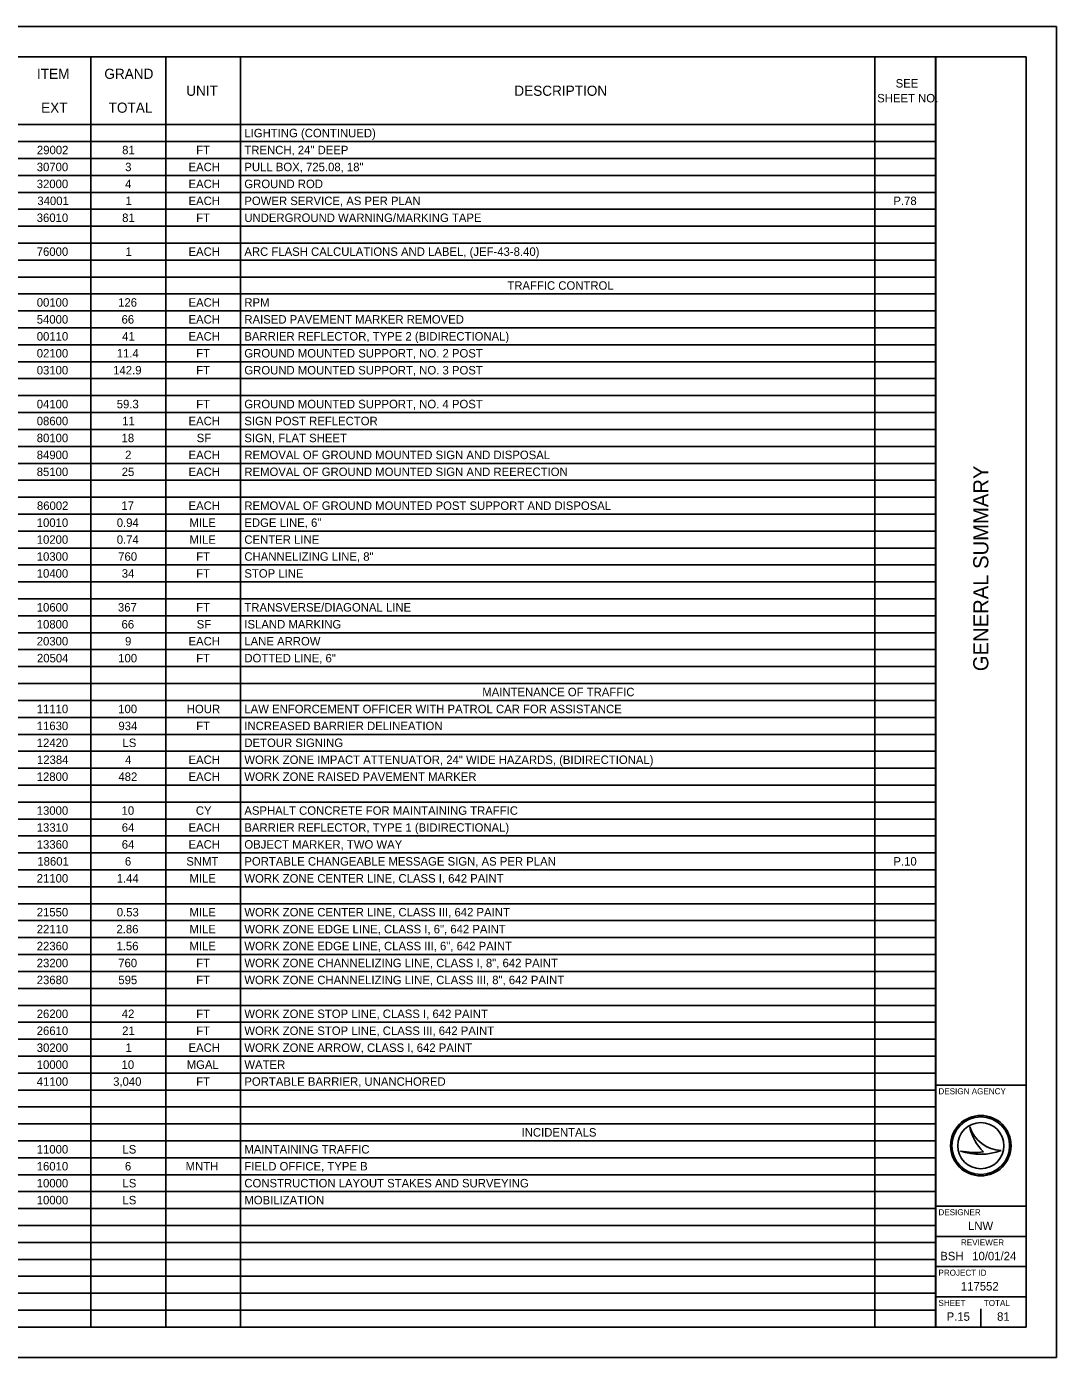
# Model space of a CAD drawing. Extents: x 0 to 34, y 0 to 22.
# Drawn here: x 16.97 to 34, y 0 to 22 of the extents above; entities that cross this region are included whole.
import ezdxf

# ---------------------------------------------------------------- set-up
doc = ezdxf.new("R2010")
doc.units = 0
for name, color, linetype in [('Default', 7, 'Continuous'), ('SH_Border', 7, 'Continuous'), ('SH_Cut_Line', 7, 'Continuous'), ('SH_Data', 7, 'Continuous')]:
    doc.layers.add(name, color=color, linetype=linetype)

msp = doc.modelspace()

# ---------------------------------------------------------------- linework, layer by layer
at = {"layer": 'Default'}
for p, q in [((1.5, 21.5), (32.004, 21.5)), ((18.036, 21.5), (18.036, 0.5)), ((19.272, 21.5), (19.272, 0.5)), ((20.507, 21.5), (20.507, 0.5)), ((30.999, 21.5), (30.999, 0.5)), ((32.004, 21.5), (32.004, 0.5)), ((1.5, 20.38), (32.004, 20.38)), ((1.5, 20.1), (32.004, 20.1)), ((1.5, 19.82), (32.004, 19.82)), ((1.5, 19.54), (32.004, 19.54)), ((1.5, 19.26), (32.004, 19.26)), ((1.5, 18.98), (32.004, 18.98)), ((1.5, 18.7), (32.004, 18.7)), ((1.5, 18.42), (32.004, 18.42)), ((1.5, 18.14), (32.004, 18.14)), ((1.5, 17.86), (32.004, 17.86)), ((1.5, 17.58), (32.004, 17.58)), ((1.5, 17.3), (32.004, 17.3)), ((1.5, 17.02), (32.004, 17.02)), ((1.5, 16.74), (32.004, 16.74)), ((1.5, 16.46), (32.004, 16.46)), ((1.5, 16.18), (32.004, 16.18)), ((1.5, 15.9), (32.004, 15.9)), ((1.5, 15.62), (32.004, 15.62)), ((1.5, 15.34), (32.004, 15.34)), ((1.5, 15.06), (32.004, 15.06)), ((1.5, 14.78), (32.004, 14.78)), ((1.5, 14.5), (32.004, 14.5)), ((1.5, 14.22), (32.004, 14.22)), ((1.5, 13.94), (32.004, 13.94)), ((1.5, 13.66), (32.004, 13.66)), ((1.5, 13.38), (32.004, 13.38)), ((1.5, 13.1), (32.004, 13.1)), ((1.5, 12.82), (32.004, 12.82)), ((1.5, 12.54), (32.004, 12.54)), ((1.5, 12.26), (32.004, 12.26)), ((1.5, 11.98), (32.004, 11.98)), ((1.5, 11.7), (32.004, 11.7)), ((1.5, 11.42), (32.004, 11.42)), ((1.5, 11.14), (32.004, 11.14)), ((1.5, 10.86), (32.004, 10.86)), ((1.5, 10.58), (32.004, 10.58)), ((1.5, 10.3), (32.004, 10.3)), ((1.5, 10.02), (32.004, 10.02)), ((1.5, 9.74), (32.004, 9.74)), ((1.5, 9.46), (32.004, 9.46)), ((1.5, 9.18), (32.004, 9.18)), ((1.5, 8.9), (32.004, 8.9)), ((1.5, 8.62), (32.004, 8.62)), ((1.5, 8.34), (32.004, 8.34)), ((1.5, 8.06), (32.004, 8.06)), ((1.5, 7.78), (32.004, 7.78)), ((1.5, 7.5), (32.004, 7.5)), ((1.5, 7.22), (32.004, 7.22)), ((1.5, 6.94), (32.004, 6.94)), ((1.5, 6.66), (32.004, 6.66)), ((1.5, 6.38), (32.004, 6.38)), ((1.5, 6.1), (32.004, 6.1)), ((1.5, 5.82), (32.004, 5.82)), ((1.5, 5.54), (32.004, 5.54)), ((1.5, 5.26), (32.004, 5.26)), ((1.5, 4.98), (32.004, 4.98)), ((1.5, 4.7), (32.004, 4.7)), ((1.5, 4.42), (32.004, 4.42)), ((1.5, 4.14), (32.004, 4.14)), ((1.5, 3.86), (32.004, 3.86)), ((1.5, 3.58), (32.004, 3.58)), ((1.5, 3.3), (32.004, 3.3)), ((1.5, 3.02), (32.004, 3.02)), ((1.5, 2.74), (32.004, 2.74)), ((1.5, 2.46), (32.004, 2.46)), ((1.5, 2.18), (32.004, 2.18)), ((1.5, 1.9), (32.004, 1.9)), ((1.5, 1.62), (32.004, 1.62)), ((1.5, 1.34), (32.004, 1.34)), ((1.5, 1.06), (32.004, 1.06)), ((1.5, 0.78), (32.004, 0.78)), ((1.5, 0.5), (32.004, 0.5))]:
    msp.add_line(p, q, dxfattribs=at)
at = {"layer": 'SH_Border'}
for p, q in [((32, 0.5), (32, 21.5)), ((32, 4.5), (33.5, 4.5)), ((32, 2.5), (33.5, 2.5)), ((32, 2), (33.5, 2)), ((32, 1.5), (33.5, 1.5)), ((32, 1), (33.5, 1))]:
    msp.add_line(p, q, dxfattribs=at)
msp.add_lwpolyline([(1.5, 21.5), (33.5, 21.5), (33.5, 0.5), (1.5, 0.5)], close=True, dxfattribs=at)
at = {"layer": 'SH_Cut_Line'}
msp.add_lwpolyline([(0, 0), (34, 0), (34, 22), (0, 22)], close=True, dxfattribs=at)
at = {"layer": 'SH_Data'}
for p, q in [((32.567, 3.81), (32.567, 3.81)), ((32.417, 3.41), (32.417, 3.41)), ((32.75, 3.5), (32.75, 3.5)), ((33.087, 3.419), (33.087, 3.419)), ((32.375, 0.675), (32.375, 0.675)), ((32.75, 0.5), (32.75, 0.8))]:
    msp.add_line(p, q, dxfattribs=at)
for radius in [0.5, 0.477, 0.477, 0.382]:
    msp.add_circle((32.75, 3.5), radius, dxfattribs=at)
for centre, radius, start, end in [((33.116, 3.998), 0.58, 198.9257, 198.9319), ((33.347, 3.97), 0.796, 191.6379, 191.6421), ((33.116, 3.998), 0.58, 198.9319, 267.1657), ((33.347, 3.97), 0.796, 191.6421, 226.0947), ((32.739, 4.37), 1.013, 251.4576, 290.0832), ((32.648, 4.654), 1.266, 259.4964, 259.4995), ((32.739, 4.37), 1.013, 251.4527, 251.4576), ((32.648, 4.654), 1.266, 259.4995, 276.6672)]:
    msp.add_arc(centre, radius, start, end, dxfattribs=at)

# ---------------------------------------------------------------- texts
at = {"layer": 'Default'}
for s, height, p in [('ITEM', 0.168, (17.144, 21.136)), ('GRAND', 0.168, (18.258, 21.136)), ('SEE ', 0.14, (31.342, 20.992)), ('UNIT', 0.168, (19.612, 20.856)), ('DESCRIPTION', 0.168, (25.037, 20.856)), ('EXT', 0.168, (17.212, 20.576)), ('TOTAL', 0.168, (18.329, 20.576)), ('SHEET NO.', 0.14, (31.037, 20.747)), ('LIGHTING (CONTINUED)', 0.14, (20.573, 20.17)), ('29002', 0.14, (17.143, 19.89)), ('81', 0.14, (18.552, 19.89)), ('FT', 0.14, (19.777, 19.89)), ('TRENCH, 24" DEEP', 0.14, (20.573, 19.89)), ('30700', 0.14, (17.14, 19.61)), ('3', 0.14, (18.602, 19.61)), ('EACH', 0.14, (19.65, 19.61)), ('PULL BOX, 725.08, 18"', 0.14, (20.573, 19.61)), ('32000', 0.14, (17.14, 19.33)), ('4', 0.14, (18.602, 19.33)), ('EACH', 0.14, (19.65, 19.33)), ('GROUND ROD', 0.14, (20.573, 19.33)), ('34001', 0.14, (17.15, 19.05)), ('1', 0.14, (18.608, 19.05)), ('EACH', 0.14, (19.65, 19.05)), ('POWER SERVICE, AS PER PLAN', 0.14, (20.573, 19.05)), ('P.78', 0.14, (31.305, 19.05)), ('36010', 0.14, (17.14, 18.77)), ('81', 0.14, (18.552, 18.77)), ('FT', 0.14, (19.777, 18.77)), ('UNDERGROUND WARNING/MARKING TAPE', 0.14, (20.573, 18.77)), ('76000', 0.14, (17.14, 18.21)), ('1', 0.14, (18.608, 18.21)), ('EACH', 0.14, (19.65, 18.21)), ('ARC FLASH CALCULATIONS AND LABEL, (JEF-43-8.40)', 0.14, (20.573, 18.21)), ('TRAFFIC CONTROL', 0.14, (24.922, 17.65)), ('00100', 0.14, (17.14, 17.37)), ('126', 0.14, (18.486, 17.37)), ('EACH', 0.14, (19.65, 17.37)), ('RPM', 0.14, (20.573, 17.37)), ('54000', 0.14, (17.14, 17.09)), ('66', 0.14, (18.542, 17.09)), ('EACH', 0.14, (19.65, 17.09)), ('RAISED PAVEMENT MARKER REMOVED', 0.14, (20.573, 17.09)), ('00110', 0.14, (17.14, 16.81)), ('41', 0.14, (18.552, 16.81)), ('EACH', 0.14, (19.65, 16.81)), ('BARRIER REFLECTOR, TYPE 2 (BIDIRECTIONAL)', 0.14, (20.573, 16.81)), ('02100', 0.14, (17.14, 16.53)), ('11.4', 0.14, (18.463, 16.53)), ('FT', 0.14, (19.777, 16.53)), ('GROUND MOUNTED SUPPORT, NO. 2 POST', 0.14, (20.573, 16.53)), ('03100', 0.14, (17.14, 16.25)), ('142.9', 0.14, (18.404, 16.25)), ('FT', 0.14, (19.777, 16.25)), ('GROUND MOUNTED SUPPORT, NO. 3 POST', 0.14, (20.573, 16.25)), ('04100', 0.14, (17.14, 15.69)), ('59.3', 0.14, (18.463, 15.69)), ('FT', 0.14, (19.777, 15.69)), ('GROUND MOUNTED SUPPORT, NO. 4 POST', 0.14, (20.573, 15.69)), ('08600', 0.14, (17.14, 15.41)), ('11', 0.14, (18.552, 15.41)), ('EACH', 0.14, (19.65, 15.41)), ('SIGN POST REFLECTOR', 0.14, (20.573, 15.41)), ('80100', 0.14, (17.14, 15.13)), ('18', 0.14, (18.543, 15.13)), ('SF', 0.14, (19.785, 15.13)), ('SIGN, FLAT SHEET', 0.14, (20.573, 15.13)), ('84900', 0.14, (17.14, 14.85)), ('2', 0.14, (18.602, 14.85)), ('EACH', 0.14, (19.65, 14.85)), ('REMOVAL OF GROUND MOUNTED SIGN AND DISPOSAL', 0.14, (20.573, 14.85)), ('85100', 0.14, (17.14, 14.57)), ('25', 0.14, (18.545, 14.57)), ('EACH', 0.14, (19.65, 14.57)), ('REMOVAL OF GROUND MOUNTED SIGN AND REERECTION', 0.14, (20.573, 14.57)), ('86002', 0.14, (17.143, 14.01)), ('17', 0.14, (18.539, 14.01)), ('EACH', 0.14, (19.65, 14.01)), ('REMOVAL OF GROUND MOUNTED POST SUPPORT AND DISPOSAL', 0.14, (20.573, 14.01)), ('10010', 0.14, (17.14, 13.73)), ('0.94', 0.14, (18.463, 13.73)), ('MILE', 0.14, (19.665, 13.73)), ('EDGE LINE, 6"', 0.14, (20.573, 13.73)), ('10200', 0.14, (17.14, 13.45)), ('0.74', 0.14, (18.463, 13.45)), ('MILE', 0.14, (19.665, 13.45)), ('CENTER LINE', 0.14, (20.573, 13.45)), ('10300', 0.14, (17.14, 13.17)), ('760', 0.14, (18.487, 13.17)), ('FT', 0.14, (19.777, 13.17)), ('CHANNELIZING LINE, 8"', 0.14, (20.573, 13.17)), ('10400', 0.14, (17.14, 12.89)), ('34', 0.14, (18.546, 12.89)), ('FT', 0.14, (19.777, 12.89)), ('STOP LINE', 0.14, (20.573, 12.89)), ('10600', 0.14, (17.14, 12.33)), ('367', 0.14, (18.483, 12.33)), ('FT', 0.14, (19.777, 12.33)), ('TRANSVERSE/DIAGONAL LINE', 0.14, (20.573, 12.33)), ('10800', 0.14, (17.14, 12.05)), ('66', 0.14, (18.542, 12.05)), ('SF', 0.14, (19.785, 12.05)), ('ISLAND MARKING', 0.14, (20.573, 12.05)), ('20300', 0.14, (17.14, 11.77)), ('9', 0.14, (18.6, 11.77)), ('EACH', 0.14, (19.65, 11.77)), ('LANE ARROW', 0.14, (20.573, 11.77)), ('20504', 0.14, (17.144, 11.49)), ('100', 0.14, (18.487, 11.49)), ('FT', 0.14, (19.777, 11.49)), ('DOTTED LINE, 6"', 0.14, (20.573, 11.49)), ('MAINTENANCE OF TRAFFIC', 0.14, (24.507, 10.93)), ('11110', 0.14, (17.14, 10.65)), ('100', 0.14, (18.487, 10.65)), ('HOUR', 0.14, (19.621, 10.65)), ('LAW ENFORCEMENT OFFICER WITH PATROL CAR FOR ASSISTANCE', 0.14, (20.573, 10.65)), ('11630', 0.14, (17.14, 10.37)), ('934', 0.14, (18.491, 10.37)), ('FT', 0.14, (19.777, 10.37)), ('INCREASED BARRIER DELINEATION', 0.14, (20.573, 10.37)), ('12420', 0.14, (17.14, 10.09)), ('LS', 0.14, (18.558, 10.09)), ('DETOUR SIGNING', 0.14, (20.573, 10.09)), ('12384', 0.14, (17.144, 9.81)), ('4', 0.14, (18.602, 9.81)), ('EACH', 0.14, (19.65, 9.81)), ('WORK ZONE IMPACT ATTENUATOR, 24" WIDE HAZARDS, (BIDIRECTIONAL)', 0.14, (20.573, 9.81)), ('12800', 0.14, (17.14, 9.53)), ('482', 0.14, (18.49, 9.53)), ('EACH', 0.14, (19.65, 9.53)), ('WORK ZONE RAISED PAVEMENT MARKER', 0.14, (20.573, 9.53)), ('13000', 0.14, (17.14, 8.97)), ('10', 0.14, (18.543, 8.97)), ('CY', 0.14, (19.771, 8.97)), ('ASPHALT CONCRETE FOR MAINTAINING TRAFFIC', 0.14, (20.573, 8.97)), ('13310', 0.14, (17.14, 8.69)), ('64', 0.14, (18.546, 8.69)), ('EACH', 0.14, (19.65, 8.69)), ('BARRIER REFLECTOR, TYPE 1 (BIDIRECTIONAL)', 0.14, (20.573, 8.69)), ('13360', 0.14, (17.14, 8.41)), ('64', 0.14, (18.546, 8.41)), ('EACH', 0.14, (19.65, 8.41)), ('OBJECT MARKER, TWO WAY', 0.14, (20.573, 8.41)), ('18601', 0.14, (17.15, 8.13)), ('6', 0.14, (18.598, 8.13)), ('SNMT', 0.14, (19.613, 8.13)), ('PORTABLE CHANGEABLE MESSAGE SIGN, AS PER PLAN', 0.14, (20.573, 8.13)), ('P.10', 0.14, (31.305, 8.13)), ('21100', 0.14, (17.14, 7.85)), ('1.44', 0.14, (18.463, 7.85)), ('MILE', 0.14, (19.665, 7.85)), ('WORK ZONE CENTER LINE, CLASS I, 642 PAINT', 0.14, (20.573, 7.85)), ('21550', 0.14, (17.14, 7.29)), ('0.53', 0.14, (18.463, 7.29)), ('MILE', 0.14, (19.665, 7.29)), ('WORK ZONE CENTER LINE, CLASS III, 642 PAINT', 0.14, (20.573, 7.29)), ('22110', 0.14, (17.14, 7.01)), ('2.86', 0.14, (18.458, 7.01)), ('MILE', 0.14, (19.665, 7.01)), ('WORK ZONE EDGE LINE, CLASS I, 6", 642 PAINT', 0.14, (20.573, 7.01)), ('22360', 0.14, (17.14, 6.73)), ('1.56', 0.14, (18.458, 6.73)), ('MILE', 0.14, (19.665, 6.73)), ('WORK ZONE EDGE LINE, CLASS III, 6", 642 PAINT', 0.14, (20.573, 6.73)), ('23200', 0.14, (17.14, 6.45)), ('760', 0.14, (18.487, 6.45)), ('FT', 0.14, (19.777, 6.45)), ('WORK ZONE CHANNELIZING LINE, CLASS I, 8", 642 PAINT', 0.14, (20.573, 6.45)), ('23680', 0.14, (17.14, 6.17)), ('595', 0.14, (18.489, 6.17)), ('FT', 0.14, (19.777, 6.17)), ('WORK ZONE CHANNELIZING LINE, CLASS III, 8", 642 PAINT', 0.14, (20.573, 6.17)), ('26200', 0.14, (17.14, 5.61)), ('42', 0.14, (18.546, 5.61)), ('FT', 0.14, (19.777, 5.61)), ('WORK ZONE STOP LINE, CLASS I, 642 PAINT', 0.14, (20.573, 5.61)), ('26610', 0.14, (17.14, 5.33)), ('21', 0.14, (18.552, 5.33)), ('FT', 0.14, (19.777, 5.33)), ('WORK ZONE STOP LINE, CLASS III, 642 PAINT', 0.14, (20.573, 5.33)), ('30200', 0.14, (17.14, 5.05)), ('1', 0.14, (18.608, 5.05)), ('EACH', 0.14, (19.65, 5.05)), ('WORK ZONE ARROW, CLASS I, 642 PAINT', 0.14, (20.573, 5.05)), ('10000', 0.14, (17.14, 4.77)), ('10', 0.14, (18.543, 4.77)), ('MGAL', 0.14, (19.62, 4.77)), ('WATER', 0.14, (20.573, 4.77)), ('41100', 0.14, (17.14, 4.49)), ('3,040', 0.14, (18.403, 4.49)), ('FT', 0.14, (19.777, 4.49)), ('PORTABLE BARRIER, UNANCHORED', 0.14, (20.573, 4.49)), ('INCIDENTALS', 0.14, (25.157, 3.65)), ('11000', 0.14, (17.14, 3.37)), ('LS', 0.14, (18.558, 3.37)), ('MAINTAINING TRAFFIC', 0.14, (20.573, 3.37)), ('16010', 0.14, (17.14, 3.09)), ('6', 0.14, (18.598, 3.09)), ('MNTH', 0.14, (19.602, 3.09)), ('FIELD OFFICE, TYPE B', 0.14, (20.573, 3.09)), ('10000', 0.14, (17.14, 2.81)), ('LS', 0.14, (18.558, 2.81)), ('CONSTRUCTION LAYOUT STAKES AND SURVEYING', 0.14, (20.573, 2.81)), ('10000', 0.14, (17.14, 2.53)), ('LS', 0.14, (18.558, 2.53)), ('MOBILIZATION', 0.14, (20.573, 2.53))]:
    msp.add_text(s, height=height, dxfattribs=at).set_placement(p)
at = {"layer": 'SH_Data'}
msp.add_text('GENERAL SUMMARY', height=0.25, rotation=90, dxfattribs=at).set_placement((32.875, 11.344))
for s, height, p in [('DESIGN AGENCY', 0.1, (32.05, 4.35)), ('DESIGNER', 0.1, (32.05, 2.35)), ('LNW', 0.14, (32.538, 2.105)), ('REVIEWER', 0.1, (32.422, 1.85)), ('BSH', 0.14, (32.08, 1.605)), ('10/01/24', 0.14, (32.608, 1.605)), ('PROJECT ID', 0.1, (32.05, 1.35)), ('117552', 0.14, (32.421, 1.105)), ('SHEET', 0.1, (32.05, 0.85)), ('TOTAL', 0.1, (32.8, 0.85)), ('P.15', 0.14, (32.185, 0.605)), ('81', 0.14, (33.019, 0.605))]:
    msp.add_text(s, height=height, dxfattribs=at).set_placement(p)

doc.saveas('drawing.dxf')
